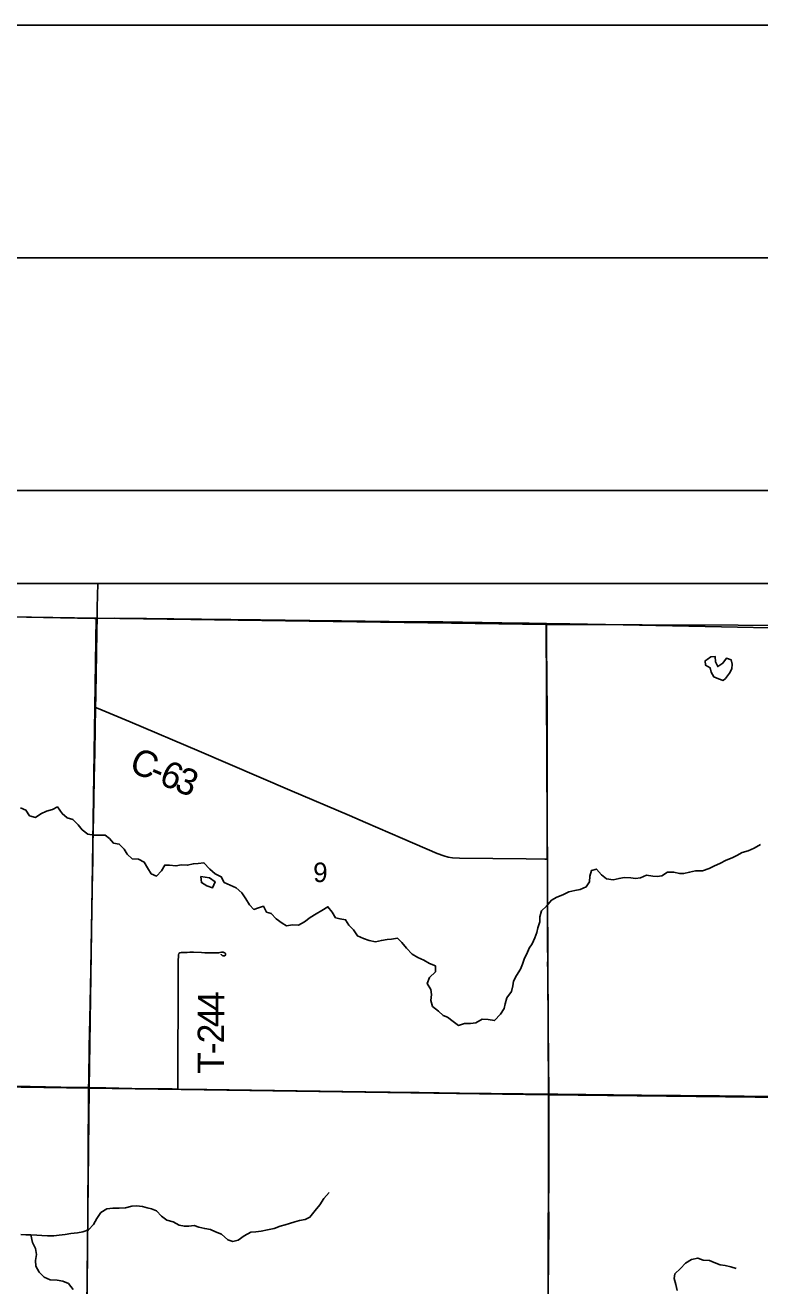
# Model space of a CAD drawing. Extents: x 0 to 34, y 0 to 22.
# Drawn here: x 4.92 to 6.5, y 19.29 to 22 of the extents above; entities that cross this region are included whole.
import ezdxf

# ---------------------------------------------------------------- set-up
doc = ezdxf.new("R2010")
doc.units = 0
for name, color, linetype in [('Default', 7, 'Continuous'), ('GM_X_City_Street', 7, 'Continuous'), ('GM_X_County_Road_Text', 7, 'Continuous'), ('GM_X_Interchange_Ramps', 7, 'Continuous'), ('GM_X_Major_River', 7, 'Continuous'), ('GM_X_Major_River_Text', 7, 'Continuous'), ('GM_X_Minor_River_Text', 7, 'Continuous'), ('GM_X_Section', 7, 'Continuous'), ('GM_X_Unincorporated_Location', 7, 'Continuous'), ('SH_Cut_Line', 7, 'Continuous'), ('SH_Data', 7, 'Continuous'), ('SH_Text', 7, 'Continuous')]:
    doc.layers.add(name, color=color, linetype=linetype)

msp = doc.modelspace()

# ---------------------------------------------------------------- linework, layer by layer
at = {"layer": 'Default'}
msp.add_lwpolyline([(8.1282, 20.8), (2.9842, 20.8)], dxfattribs=at)
at = {"layer": 'GM_X_City_Street'}
for points in [[(5.0748, 20.7246), (5.0749, 20.7294), (5.0749, 20.7481), (5.0762, 20.8)], [(3.7953, 20.743), (3.8947, 20.7428), (4.0314, 20.7415), (4.1153, 20.7402), (4.2456, 20.738), (4.3637, 20.7359), (4.4476, 20.7347), (4.4849, 20.7344), (4.5222, 20.7338), (4.5875, 20.7327), (4.6714, 20.7316), (4.7397, 20.7306), (4.8081, 20.7293), (4.9231, 20.7277), (5.0691, 20.7246), (5.0748, 20.7246)], [(5.0714, 20.5333), (5.0719, 20.5585), (5.073, 20.6082), (5.0732, 20.6457), (5.0744, 20.6989), (5.0748, 20.7246)], [(5.0748, 20.7246), (5.1126, 20.7251), (5.181, 20.7242), (5.2991, 20.7232), (5.4265, 20.7216), (5.5322, 20.7204), (5.6005, 20.7196), (5.7031, 20.7182), (5.7466, 20.7176), (5.8181, 20.7172), (5.9455, 20.7155), (6.0045, 20.7144), (6.0415, 20.7139)], [(6.0415, 20.7139), (6.0915, 20.7133), (6.2065, 20.7107), (6.4178, 20.7065), (6.5545, 20.704), (6.5629, 20.7041)], [(6.0434, 20.207), (6.0431, 20.2605), (6.0428, 20.4034), (6.0428, 20.5216), (6.0417, 20.6708), (6.0415, 20.708), (6.0415, 20.7139)], [(5.056, 19.7161), (5.0566, 19.7323), (5.0579, 19.8037), (5.0588, 19.8628), (5.061, 19.9684), (5.0624, 20.0585), (5.0643, 20.1393), (5.0649, 20.1796), (5.0652, 20.2014), (5.0658, 20.2355), (5.0666, 20.2697), (5.0672, 20.2976), (5.0679, 20.3349), (5.0687, 20.3815), (5.0696, 20.4374), (5.0705, 20.4871), (5.0714, 20.5333)], [(5.0714, 20.5333), (5.0768, 20.531), (5.1458, 20.5024), (5.2946, 20.439), (5.489, 20.3556), (5.6177, 20.3008), (5.652, 20.2861), (5.732, 20.2518), (5.8062, 20.2195), (5.8207, 20.214), (5.8297, 20.2116), (5.8389, 20.2101), (5.8545, 20.2091), (5.9976, 20.2077), (6.038, 20.2071), (6.0434, 20.207)], [(6.0463, 19.7017), (6.0462, 19.7092), (6.0459, 19.7682), (6.0458, 19.7869), (6.0453, 19.8366), (6.0453, 19.8739), (6.0445, 19.9324), (6.0443, 19.9665), (6.0439, 19.9854), (6.044, 19.9871), (6.044, 19.9932), (6.0438, 20.0179), (6.0436, 20.046), (6.0434, 20.0522), (6.0433, 20.0709), (6.0433, 20.1019), (6.0433, 20.1486), (6.0435, 20.1921), (6.0434, 20.207)], [(4.0339, 19.7324), (4.0588, 19.7321), (4.1116, 19.7314), (4.2048, 19.7299), (4.3135, 19.728), (4.4161, 19.7264), (4.559, 19.7241), (4.6428, 19.7226), (4.7764, 19.7203), (4.8976, 19.7188), (4.997, 19.7167), (5.056, 19.7161)], [(5.05, 18.7053), (5.0501, 18.7132), (5.0503, 18.7629), (5.0507, 18.8157), (5.051, 18.8437), (5.0514, 18.8903), (5.0516, 18.9431), (5.0519, 18.9897), (5.0523, 19.0425), (5.0526, 19.0829), (5.0527, 19.1326), (5.0532, 19.201), (5.0535, 19.2258), (5.0537, 19.2973), (5.0539, 19.3563), (5.054, 19.3874), (5.0546, 19.4278), (5.055, 19.4806), (5.0554, 19.5334), (5.0554, 19.5863), (5.0563, 19.6888), (5.056, 19.7161)], [(5.056, 19.7161), (5.0933, 19.7153), (5.1492, 19.7143), (5.2362, 19.7131), (5.2482, 19.7129)], [(5.2482, 19.7129), (5.3108, 19.7121), (5.4071, 19.7107), (5.6525, 19.7069), (5.7053, 19.7065), (5.7675, 19.7055), (5.8545, 19.7042), (5.9912, 19.7023), (6.0463, 19.7017)], [(6.0443, 18.6905), (6.0443, 18.699), (6.0442, 18.727), (6.0449, 18.8855), (6.0452, 18.9819), (6.0454, 19.1342), (6.0454, 19.1994), (6.0452, 19.2461), (6.0451, 19.2771), (6.0458, 19.3486), (6.0463, 19.4294), (6.0459, 19.4698), (6.0462, 19.5071), (6.0463, 19.6066), (6.0465, 19.6781), (6.0463, 19.7017)], [(6.0463, 19.7017), (6.0657, 19.7015), (6.2459, 19.6996), (6.4137, 19.6984), (6.5194, 19.697), (6.5659, 19.6962), (6.6498, 19.6948), (6.7181, 19.6932), (6.8087, 19.6918)]]:
    msp.add_lwpolyline(points, dxfattribs=at)
at = {"layer": 'GM_X_Interchange_Ramps'}
for points in [[(5.2496, 19.9959), (5.2497, 20.0011), (5.2507, 20.004), (5.253, 20.0059), (5.256, 20.0067), (5.2684, 20.0066), (5.274, 20.0068), (5.2822, 20.0068), (5.299, 20.0062), (5.3066, 20.0059), (5.31, 20.0057), (5.325, 20.0057), (5.3337, 20.0059), (5.3364, 20.006), (5.3392, 20.0065), (5.3422, 20.0069), (5.3432, 20.007), (5.3443, 20.0069), (5.3452, 20.0069), (5.3462, 20.0068), (5.3471, 20.0066), (5.3481, 20.0063), (5.3489, 20.0059), (5.3495, 20.0054), (5.3501, 20.0049), (5.3507, 20.0037), (5.3508, 20.0029), (5.3509, 20.002), (5.3508, 20.0013), (5.3503, 19.9999), (5.3497, 19.9993), (5.349, 19.999), (5.348, 19.999), (5.3469, 19.9991), (5.3463, 19.9992), (5.3455, 19.9995), (5.3442, 19.9999), (5.3435, 20.0003), (5.3429, 20.0007), (5.3418, 20.0019), (5.3414, 20.0026)], [(5.2482, 19.7129), (5.2482, 19.7183), (5.2482, 19.7805), (5.2491, 19.9016), (5.2494, 19.9483), (5.2494, 19.9918), (5.2496, 19.9959)], [(4.0339, 19.7324), (4.0588, 19.7321), (4.1116, 19.7314), (4.2048, 19.7299), (4.3135, 19.728), (4.4161, 19.7264), (4.559, 19.7241), (4.6428, 19.7226), (4.7764, 19.7203), (4.8976, 19.7188), (4.997, 19.7167), (5.056, 19.7161)], [(5.056, 19.7161), (5.0933, 19.7153), (5.1492, 19.7143), (5.2362, 19.7131), (5.2482, 19.7129)], [(5.2482, 19.7129), (5.3108, 19.7121), (5.4071, 19.7107), (5.6525, 19.7069), (5.7053, 19.7065), (5.7675, 19.7055), (5.8545, 19.7042), (5.9912, 19.7023), (6.0463, 19.7017)], [(6.0463, 19.7017), (6.0657, 19.7015), (6.2459, 19.6996), (6.4137, 19.6984), (6.5194, 19.697), (6.5659, 19.6962), (6.6498, 19.6948), (6.7181, 19.6932), (6.8087, 19.6918)]]:
    msp.add_lwpolyline(points, dxfattribs=at)
at = {"layer": 'GM_X_Major_River'}
for points in [[(6.3868, 20.6364), (6.383, 20.6336), (6.3835, 20.6241), (6.3932, 20.6185), (6.396, 20.609), (6.4014, 20.5989), (6.4115, 20.5949), (6.4216, 20.5915), (6.4266, 20.5952)], [(6.4266, 20.5952), (6.4353, 20.6067), (6.4401, 20.6165), (6.4411, 20.6263), (6.4384, 20.6359), (6.4286, 20.6392), (6.4208, 20.6288), (6.4099, 20.6211), (6.4049, 20.6311), (6.4041, 20.6429), (6.3946, 20.6421), (6.3868, 20.6364)], [(5.2977, 20.1695), (5.2992, 20.1566), (5.311, 20.1494), (5.3232, 20.1457), (5.326, 20.1519)], [(5.326, 20.1519), (5.3288, 20.1582), (5.3163, 20.1669), (5.2977, 20.1695)]]:
    msp.add_lwpolyline(points, dxfattribs=at)
at = {"layer": 'GM_X_Section'}
for points in [[(4.9099, 20.3176), (4.9216, 20.3127), (4.9296, 20.3006), (4.9422, 20.2968), (4.9539, 20.3048), (4.966, 20.3106), (4.9789, 20.3137), (4.9895, 20.3194), (4.9994, 20.3054), (5.0101, 20.2959), (5.0222, 20.2922), (5.034, 20.2812), (5.0428, 20.2703), (5.0546, 20.2608), (5.0683, 20.259), (5.0921, 20.259), (5.1017, 20.2515), (5.1097, 20.2417), (5.1222, 20.2394), (5.1328, 20.2288), (5.1397, 20.2175), (5.1504, 20.2077), (5.164, 20.2073), (5.1762, 20.2009), (5.1834, 20.1888), (5.1911, 20.1759), (5.2025, 20.1707), (5.2134, 20.1817), (5.2202, 20.1942), (5.2308, 20.1939), (5.2441, 20.1924), (5.2566, 20.1951), (5.2688, 20.194), (5.282, 20.1971), (5.2919, 20.1975), (5.3044, 20.1994), (5.317, 20.1858), (5.3284, 20.1753), (5.3417, 20.1689), (5.3482, 20.1571), (5.374, 20.1458), (5.3862, 20.1349), (5.395, 20.122), (5.4026, 20.1091), (5.4117, 20.0989), (5.422, 20.1027), (5.4326, 20.1058), (5.4394, 20.0933), (5.4493, 20.0903), (5.46, 20.0786), (5.4725, 20.0695), (5.482, 20.0639), (5.4949, 20.0658), (5.5078, 20.0651), (5.5211, 20.0727), (5.5328, 20.0815), (5.5457, 20.0895), (5.5585, 20.0964), (5.5714, 20.1048), (5.5802, 20.0934), (5.5878, 20.0813), (5.5973, 20.0787), (5.6094, 20.0768), (5.6159, 20.0651), (5.6262, 20.0553), (5.635, 20.042), (5.6475, 20.0364), (5.6601, 20.0319), (5.6737, 20.0296), (5.6862, 20.0323), (5.6984, 20.0343), (5.7078, 20.0354), (5.7207, 20.037), (5.7302, 20.0279), (5.7401, 20.0154), (5.7527, 20.003), (5.7645, 19.9958), (5.7774, 19.9901), (5.79, 19.9826), (5.8025, 19.9777), (5.8025, 19.9652), (5.7901, 19.953), (5.7844, 19.9401), (5.7924, 19.9272), (5.794, 19.9159), (5.7929, 19.903), (5.796, 19.8905), (5.8089, 19.8803), (5.8192, 19.8708), (5.8287, 19.8671), (5.8405, 19.8584), (5.8519, 19.8497), (5.8651, 19.8539), (5.8777, 19.8536), (5.8894, 19.8551), (5.9027, 19.8628), (5.9163, 19.8624), (5.9296, 19.8602), (5.9425, 19.8739)], [(5.9425, 19.8739), (5.9504, 19.886), (5.9526, 19.8959), (5.956, 19.9088), (5.9658, 19.9225), (5.9692, 19.935), (5.9707, 19.9449), (5.9767, 19.9571), (5.9854, 19.9704), (5.9899, 19.981), (5.994, 19.9939), (5.9989, 20.0038), (6.0042, 20.0159), (6.0106, 20.0254), (6.0162, 20.0376), (6.0204, 20.0497), (6.023, 20.0596), (6.0271, 20.0721), (6.0274, 20.0831), (6.0308, 20.096), (6.0418, 20.1063), (6.052, 20.1189), (6.0637, 20.1254), (6.0766, 20.1307), (6.0895, 20.1372), (6.1024, 20.1399), (6.1141, 20.1422), (6.127, 20.1476), (6.1342, 20.1582), (6.1345, 20.1707), (6.1379, 20.1829), (6.1492, 20.1859), (6.1595, 20.1735), (6.1705, 20.1648), (6.1846, 20.1625), (6.1975, 20.1656), (6.2088, 20.1676), (6.2225, 20.1672), (6.2331, 20.1657), (6.2434, 20.1669), (6.2566, 20.1726), (6.2699, 20.1704), (6.2794, 20.1701), (6.2892, 20.1716), (6.3014, 20.1789), (6.315, 20.1793), (6.3275, 20.1763), (6.337, 20.1763), (6.3492, 20.179), (6.362, 20.1821), (6.3768, 20.1818), (6.3912, 20.1867), (6.4026, 20.1925), (6.414, 20.1978), (6.4276, 20.2051), (6.4408, 20.21), (6.4511, 20.215), (6.4624, 20.2215), (6.4749, 20.2253), (6.4882, 20.2307), (6.5018, 20.2383)], [(4.9108, 19.4002), (4.9214, 19.3994), (4.9321, 19.3991), (4.9453, 19.3984), (4.956, 19.3977), (4.9681, 19.3973), (4.9818, 19.3974), (4.9931, 19.3989), (5.006, 19.4001), (5.0185, 19.402), (5.0322, 19.404), (5.0443, 19.4059), (5.0565, 19.4101), (5.067, 19.4216), (5.0742, 19.4345), (5.0829, 19.4474), (5.0957, 19.455), (5.1086, 19.4566), (5.1223, 19.457), (5.1359, 19.4578), (5.1492, 19.4609), (5.1594, 19.4621), (5.1724, 19.4602), (5.1826, 19.4576), (5.1921, 19.4553), (5.2024, 19.4512), (5.213, 19.4395), (5.2248, 19.4312), (5.2381, 19.4271), (5.2514, 19.4199), (5.2624, 19.418), (5.2719, 19.4181), (5.2833, 19.4192), (5.2939, 19.4162), (5.3064, 19.4129), (5.3186, 19.4106), (5.3296, 19.4061), (5.3421, 19.4012), (5.3562, 19.3884), (5.3668, 19.3854), (5.3782, 19.3881), (5.3914, 19.3976), (5.4055, 19.4052), (5.4165, 19.406), (5.4278, 19.4076), (5.4411, 19.4103), (5.4559, 19.4134), (5.4688, 19.418), (5.479, 19.4206), (5.4885, 19.4237), (5.4998, 19.4275), (5.5104, 19.4299), (5.5222, 19.4325), (5.5324, 19.4375), (5.5437, 19.4516), (5.5539, 19.4641), (5.5626, 19.4778), (5.5736, 19.4907)], [(4.9321, 19.3991), (4.9355, 19.3832), (4.9424, 19.3699), (4.9447, 19.357), (4.9421, 19.3445), (4.9429, 19.3324), (4.9498, 19.3195), (4.9608, 19.3086), (4.9741, 19.3029), (4.9889, 19.3018), (5.0007, 19.3), (5.0129, 19.2947), (5.0231, 19.2822)], [(6.3224, 19.2797), (6.3197, 19.2926), (6.3158, 19.3059), (6.3173, 19.3153), (6.3298, 19.3271), (6.3404, 19.3385), (6.3532, 19.3466), (6.3669, 19.3493), (6.3786, 19.3451), (6.3919, 19.344), (6.4018, 19.3403), (6.4147, 19.335), (6.4261, 19.3335), (6.4383, 19.3309), (6.4496, 19.3268)]]:
    msp.add_lwpolyline(points, dxfattribs=at)
at = {"layer": 'GM_X_Unincorporated_Location'}
for points in [[(4.0503, 20.7412), (5.0724, 20.7252), (5.0575, 19.7147), (4.0319, 19.7295)], [(5.0724, 20.7252), (6.0408, 20.7118), (6.0459, 19.7005), (5.0575, 19.7147)], [(6.0408, 20.7118), (7.074, 20.7079), (7.0617, 19.6888), (6.0459, 19.7005)], [(4.0319, 19.7295), (5.0575, 19.7147), (5.0466, 18.7043), (4.0237, 18.7217)], [(5.0575, 19.7147), (6.0459, 19.7005), (6.0441, 18.6866), (5.0466, 18.7043)], [(6.0459, 19.7005), (7.0617, 19.6888), (7.0397, 18.6727), (6.0441, 18.6866)]]:
    msp.add_lwpolyline(points, close=True, dxfattribs=at)
at = {"layer": 'SH_Cut_Line'}
msp.add_line((2, 21), (9, 21), dxfattribs=at)
at = {"layer": 'SH_Data'}
msp.add_lwpolyline([(1.5, 21.5), (33.5, 21.5), (33.5, 0.5), (1.5, 0.5)], close=True, dxfattribs=at)
at = {"layer": 'SH_Text'}
for points in [[(0, 0), (34, 0), (34, 22), (0, 22)], [(2.9377, 14), (8.8, 14), (8.8, 20.8), (2.9842, 20.8), (2.984, 20.7397), (2.9904, 20.3395), (2.9796, 19.7242), (2.9753, 18.7199), (2.9708, 17.6769), (2.9623, 15.7101), (2.9479, 14.7065)]]:
    msp.add_lwpolyline(points, close=True, dxfattribs=at)

# ---------------------------------------------------------------- texts
at = {"layer": 'GM_X_County_Road_Text'}
for s, rotation, p in [('4', 89.7543, (5.3481, 19.8805)), ('4', 89.7346, (5.348, 19.8458)), ('2', 89.7237, (5.3478, 19.811)), ('T', 89.719, (5.3475, 19.7455)), ('-', 89.7203, (5.3477, 19.7879))]:
    msp.add_text(s, height=0.0568, rotation=rotation, dxfattribs=at).set_placement(p)
at = {"layer": 'GM_X_Major_River_Text'}
msp.add_text('9', height=0.0419, rotation=0, dxfattribs=at).set_placement((5.5395, 20.1578))
at = {"layer": 'GM_X_Minor_River_Text'}
for s, rotation, p in [('C', 336.8562, (5.1407, 20.3974)), ('6', 337.0732, (5.2053, 20.3698)), ('-', 336.8964, (5.1837, 20.379)), ('3', 338.0091, (5.2385, 20.3557))]:
    msp.add_text(s, height=0.0568, rotation=rotation, dxfattribs=at).set_placement(p)

doc.saveas('drawing.dxf')
